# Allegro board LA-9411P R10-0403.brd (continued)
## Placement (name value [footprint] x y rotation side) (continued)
PR620  -  [R_0402]  313.93 168.74 270 bottom
PR621  -  [R0402_0OHM]  309.35 168.74 270 bottom
PR622  -  [R_1206]  294.81 171.64 0 bottom
PR623  -  [R_0402]  307.2 151.83 90 bottom
PR624  -  [R_0402]  308.21 151.83 90 bottom
PR625  -  [R0402_0OHM]  308.85 171.03 270 top
PR626  -  [R_0402]  307.2 155.03 270 bottom
PR627  -  [R_0402]  316.29 165.75 180 top
PR628  -  [R0402_0OHM]  307.58 168.74 270 bottom
PR629  -  [R0402_0OHM]  316.29 165.75 180 bottom
PR631  -  [R_0402]  316.29 164.73 180 bottom
PR632  -  [R_0402]  313.29 164.22 180 top
PR633  -  [R_0402]  315.37 163.72 0 bottom
PR634  -  [R_0402]  294.42 144.69 0 top
PR635  -  [R0402_0OHM]  305.11 162.45 180 top
PR636  -  [R0402_0OHM]  304.2 162.45 0 bottom
PR637  -  [R_0402]  313.29 163.08 180 top
PR638  -  [R_0402]  315.37 162.7 0 bottom
PR639  -  [R_0402]  315.37 160.67 0 top
PR640  -  [R_0402]  315.37 159.65 0 bottom
PR641  -  [R0402_0OHM]  307.2 157.82 270 bottom
PR642  -  [R_0402]  316.29 160.67 180 bottom
PR643  -  [R0402_0OHM]  308.21 157.82 270 bottom
PR644  -  [R_0402]  313.29 162.19 180 top
PR645  -  [R_0402]  309.23 157.82 270 bottom
PR646  -  [R_0402]  314.31 161 270 top
PR647  -  [R_0402]  311.7 154.52 270 bottom
PR648  -  [R_0402]  310.62 154.52 270 top
PR649  -  [R_0603]  303.7 158.38 0 bottom
PR650  -  [R0402_0OHM]  313 157.02 90 top
PR651  -  [R_0402]  303.13 151.83 90 bottom
PR652  -  [R_0402]  304.15 151.83 90 bottom
PR653  -  [R_1206]  290.34 147.38 0 bottom
PR654  -  [R_0402]  305.16 151.83 90 bottom
PR655  -  [R_0402]  310.62 154.52 270 bottom
PR656  -  [R_0402]  304.15 154.11 90 bottom
PR657  -  [R0402_0OHM]  311.51 156.91 90 bottom
PR658  -  [R_0402]  312.4 156.91 90 bottom
PR659  -  [R_0402]  310.62 157.82 270 bottom
PR679  -  [R_0402]  198.48 89.6 90 top
PR680  -  [R_1206]  193.59 90.06 0 top
PR681  -  [R0402_0OHM]  202.19 92.8 270 top
PR682  -  [R_0402]  200.16 91.88 90 top
PR683  -  [R_0402]  200.77 97.88 270 top
PR684  -  [R_0402]  198.74 96.96 90 top
PR685  -  [R_0402]  280.53 136.99 270 top
PR686  -  [R_0805]  280.69 141.36 0 top
PR687  -  [R_0402]  281.8 129.48 90 top
PR688  -  [R0402_0OHM]  279.51 136.99 270 top
PR689  -  [R_0402]  280.53 132.02 90 top
PR690  -  [R_0402]  279.51 134.96 270 top
PR691  -  [R_0402]  315.37 164.73 0 top
PR692  -  [R_0402]  315.12 158.47 0 bottom
PR693  -  [R_0402]  315.96 157.44 270 bottom
PR696  -  [R0402_0OHM]  315.07 157.44 270 bottom
PR697  -  [R_0402]  317.44 157.44 270 bottom
PR700  -  [R0402_0OHM]  154.21 161.23 90 top
PR701  -  [R_1206_4P-D]  129.87 173.75 180 top
PR702  -  [R0402_0OHM]  111.62 164.53 90 top
PR703  -  [R_0402]  113.14 165.44 270 top
PR704  -  [R0402_0OHM]  80.21 190.39 0 top
PR705  -  [R0402_0OHM]  80.21 189.37 0 top
PR706  -  [R_0402]  109.33 165.44 270 top
PR707  -  [R_0402]  114.16 165.44 270 top
PR708  -  [R_0805]  84.02 187.59 180 top
PR709  -  [R0402_0OHM]  108.31 164.53 90 top
PR710  -  [R0402_0OHM]  104.81 160.67 0 top
PR713  -  [R_0402]  73.1 186.84 180 top
PR714  -  [R_0402]  75.32 185.34 0 bottom
PR715  -  [R_0603]  82.71 182.77 0 top
PR716  -  [R_1206_4P-D]  115.13 176.03 180 top
PR717  -  [R0402_0OHM]  75.22 188.48 0 top
PR718  -  [R0402_0OHM]  77.33 180.43 270 top
PR719  -  [R0402_0OHM]  76.31 180.43 270 top
PR720  -  [R_0402]  72.2 185.47 0 top
PR721  -  [R_1206]  93.75 172.12 0 bottom
PR722  -  [R_0402]  75.29 180.43 270 top
PR723  -  [R_0402]  91.25 168.03 180 top
PR724  -  [R0402_0OHM]  96.96 159.22 180 top
PR725  -  [R_0402]  93.2 166.43 90 bottom
PR726  -  [R_0402]  90.33 167.14 0 top
PR727  -  [R_0402]  105.82 162.19 0 top
PR728  -  [R_0402]  90.33 163.59 0 top
PR729  -  [R_0402]  106.74 163.21 180 top
PR730  -  [R_0402]  91.25 166.26 180 top
PR731  -  [R_0402]  93.2 165.44 270 bottom
PR732  -  [R_0402]  102.42 163.21 180 top
PR733  -  [R_0402]  102.42 165.24 180 top
PR734  -  [R_0402]  102.42 166.26 180 top
PR735  -  [R_0402]  102.42 167.27 180 top
PR736  -  [R_0402]  104.81 158.64 0 top
PR737  -  [R0402_0OHM]  101.51 166.26 0 bottom
PR738  -  [R_0402]  101.51 162.19 0 top
PR739  -  [R_0402]  101.51 165.24 0 bottom
PR740  -  [R_0402]  101.51 167.27 0 bottom
PR741  -  [R_0402]  80.88 182.23 270 top
PR742  -  [R_1206]  82.66 187.65 270 bottom
PR743  -  [R_0402]  75.32 187.12 0 bottom
PR744  -  [R_0402]  105.72 159.65 180 top
PR745  -  [R0402_0OHM]  72.2 182.82 0 top
PR746  -  [R_0402]  72.2 183.71 0 top
PR747  -  [R_0402]  72.2 184.59 0 top
PR748  -  [R_0402]  87.28 164.67 180 top
PR749  -  [R_0402]  92.74 170.07 0 top
PR800  -  [R_0402]  239.17 84.98 0 top
PR801  -  [R_0402]  54.42 190.77 180 top
PR802  -  [R_0402]  241.61 89.93 180 top
PR803  -  [R_0402]  241.92 84.01 90 top
PR804  -  [R_0402]  239.33 89.93 180 top
PR805  -  [R_0402]  241.92 81.98 90 top
PR806  -  [R_0402]  241.36 85.86 180 top
PR807  -  [R_0402]  56.24 187.79 270 top
PR808  -  [R_0402]  239.33 85.86 180 top
PR809  -  [R_0603]  242.93 73.29 180 top
PR810  -  [R_0402]  45.83 188.4 90 top
PR811  -  [R0402_0OHM]  157.64 168.15 0 top
PR812  -  [R0402_0OHM]  51.62 185.94 180 top
PR813  -  [R_0402]  123.15 182.12 270 bottom
PR814  -  [R_0402]  119.87 172.4 90 top
PR815  -  [R_0402]  122.03 173.32 270 bottom
PR816  -  [R_0402]  118.09 167.45 90 bottom
PR817  -  [R_0402]  127.62 185.48 90 top
PR818  -  [R_0402]  122.08 172.86 180 top
PR819  -  [R_0402]  78.09 172.05 270 top
PR820  -  [R0402_0OHM]  70.9 170.32 0 top
PR821  -  [R_0603]  133.52 186.45 180 bottom
PR822  -  [R_0402]  122.08 171.84 180 top
PR823  -  [R_0402]  65.39 171.39 90 top
PR824  -  [R_0402]  62.9 173.88 0 top
PR825  -  [R0402_0OHM]  63.53 170.32 0 top
PR826  -  [R_0402]  53.07 171.89 90 top
PR827  -  [R_0402]  53.07 174.05 90 top
PR828  -  [R_0402]  146.19 178.38 180 top
PR829  -  [R_0402]  59.7 175.74 270 top
PR830  -  [R_0402]  152.33 179.73 270 top
PR831  -  [R0805_0OHM]  144.28 166.73 0 top
PR832  -  [R0402_0OHM]  145.19 168.03 0 top
PR833  -  [R0402_0OHM]  147.01 165.25 270 top
PR834  -  [R_0402]  160.64 168.34 90 top
PR835  -  [R_0805]  147.68 160.32 90 top
PR836  -  [R_0402]  161.1 177.69 180 top
PR837  -  [R_0402]  161.65 168.34 90 top
PR838  -  [R0402_0OHM]  145.19 169.81 0 top
PR839  -  [R_0402]  53.07 177.25 270 top
PR840  -  [R_0402]  53.07 178.5 90 top
PR841  -  [R_0402]  161.1 178.57 180 top
PR842  -  [R_0402]  162.67 168.34 90 top
PR843  -  [R0402_0OHM]  147.18 173.42 90 top
PR844  -  [R_0402]  152.29 176.06 90 top
PR845  -  [R_0402]  162.21 177.81 0 top
PR846  -  [R_0402]  156.24 160.22 270 top
PR847  -  [R0402_0OHM]  151.56 161.14 90 top
PR848  -  [R_0402]  163.69 168.34 90 top
PR849  -  [R_0402]  59.71 177.44 90 top
PR850  -  [R0402_0OHM]  148.19 173.42 90 top
PR851  -  [R_0402]  164.7 168.34 90 top
PR852  -  [R_0402]  163.99 177.81 0 top
PR853  -  [R_0402]  166.73 168.34 90 top
PR854  -  [R0805_0OHM]  152.87 160.79 90 top
PR855  -  [R0402_0OHM]  151.24 173.42 90 top
PR856  -  [R_0402]  167.75 168.34 90 top
PR857  -  [R0402_0OHM]  152.26 173.42 90 top
PR858  -  [R_0402]  153.2 176.07 90 top
PR859  -  [R0402_0OHM]  155.23 161.23 90 top
PR860  -  [R0402_0OHM]  153.27 173.42 90 top
PR861  -  [R_0402]  167.42 177.94 0 top
PR862  -  [R0402_0OHM]  156.24 161.23 90 top
PR863  -  [R_0402]  154.29 173.42 90 top
PR864  -  [R_0402]  168.33 171.84 180 top
PR865  -  [R_0402]  167.42 176.92 0 top
PR866  -  [R0402_0OHM]  158.56 169.16 180 top
PR867  -  [R_0402]  167.42 175.91 0 top
PR868  -  [R0402_0OHM]  157.64 170.18 0 top
PR869  -  [R_0402]  156.4 173.42 90 top
PR870  -  [R_0402]  155.3 174.33 270 top
PR871  -  [R_0402]  167.42 174.89 0 top
PR872  -  [R0402_0OHM]  172.07 170.01 270 top
PR873  -  [R_0402]  167.42 173.88 0 top
PR874  -  [R_0402]  157.64 171.2 0 top
PR875  -  [R_0402]  157.46 173.42 90 top
PR876  -  [R_0402]  167.42 172.86 0 top
PR877  -  [R0805_0OHM]  157.49 166.83 0 top
PR878  -  [R_0402]  156.24 170.83 0 bottom
PR879  -  [R_0402]  157.16 172.81 180 bottom
PR880  -  [R_0402]  156.24 171.84 0 bottom
PR881  -  [R_0402]  65.85 175.67 90 top
PR882  -  [R0402_0OHM]  58.66 172.47 90 top
PR883  -  [R_0402]  155.86 177.7 0 bottom
PR884  -  [R_0402]  57.91 174.83 90 top
PR885  -  [R_0402]  57.91 178.36 270 top
PR886  -  [R0402_0OHM]  58.8 174.83 90 top
PR887  -  [R0402_0OHM]  58.82 178.36 270 top
PR888  -  [R0402_0OHM]  48.36 190.49 0 top
PR889  -  [R_0402]  116.11 172.94 90 bottom
PR890  -  [R0402_0OHM]  116.11 172.1 270 bottom
PR891  -  [R_0402]  132.88 187.27 0 top
PR892  -  [R0402_0OHM]  132.88 188.18 0 top
PR893  -  [R0402_0OHM]  145.19 168.92 0 top
PR894  -  [R_0402]  153.22 178.82 90 top
PR895  -  [R0402_0OHM]  148.22 181.84 0 top
PR896  -  [R_0402]  40.11 176.06 0 top
PR897  -  [R_0402]  41.03 177.06 180 top
PU1  -  [74LVC1G3157GW_SC-88-6]  154.4 176.3 270 bottom
PU100  -  [TPS51225CRUKR_QFN20_3X3]  151.53 4.81 180 bottom
PU200  -  [RT8207MZQW_WQFN20_3X3]  209.62 12.31 0 top
PU300  -  [TPS51212DSCR_SON10_3X3]  238.11 7.12 0 top
PU400  -  [SY8033BDBC_DFN10_3X3]  235.65 103.79 90 top
PU500  -  [ISL95812HRZ-T_QFN32_4X4]  118.21 153.43 90 bottom
PU501  -  [ISL6208BCRZ-T_QFN8_2X2]  160.91 153.69 90 top
PU600  -  [ISL62883CHRTZ-T_TQFN40_5X5]  312.72 164.75 270 bottom
PU602  -  [SY8036DBC_DFN10_3X3]  196.87 92.32 0 top
PU603  -  [SY8033BDBC_DFN10_3X3]  283.68 134.71 180 top
PU700  -  [BQ24738RGRR_QFN20_3P5X3P5]  78.58 186.4 180 top
PU701  -  [AS393MTR-G1_SO8]  93.67 167.78 270 top
PU702  -  [LM358DR2G_SOIC8]  103.19 157.24 270 top
PU703  -  [INA199A2DCKR_SC70-6]  108.43 160.58 0 top
PU704  -  [TC7SH08FU_SSOP5]  91.01 158.64 0 top
PU800  -  [CD3301RHHR_QFN36_6X6]  149.75 164.63 0 top
PU801  -  [TC7SH08FU_SSOP5]  47.72 182.83 0 top
PU802  -  [TC7SH08FU_SSOP5]  50.51 182.83 0 top
PU803  -  [74AHC1G32GW_SOT353-5]  47.97 187.4 0 top
PU804  -  [TC7SH08FU_SSOP5]  50.77 187.4 0 top
PU805  -  [TC7SH08FU_SSOP5]  76.96 173.17 180 top
PU806  -  [TC7SH08FU_SSOP5]  72.39 173.3 180 top
PU807  -  [TC7SH08FU_SSOP5]  62.41 172.75 270 top
PU808  -  [CD3302RUYR_QFN28_4X4]  161.6 171.65 0 top
PU809  -  [TC7SH08FU_SSOP5]  37.2 174.9 180 top
Q1  -  [MMBT3904WT1G_SC70-3]  145.97 96.15 90 bottom
Q2  -  [MMBT3904WT1G_SC70-3]  310.6 151.84 180 top
Q3  -  [MMBT3904WT1G_SC70-3]  161.15 132.03 0 top
Q4  -  [PMST3904_SOT323-3]  279.76 122.91 180 top
Q5  -  [L2N7002WT1G_SC-70-3]  200.94 172.73 270 bottom
Q6  -  [L2N7002WT1G_SC-70-3]  179.32 175.15 90 bottom
Q21  -  [FDC654P-G_SSOT-6]  180.73 148.41 270 bottom
Q22  -  [L2N7002WT1G_SC-70-3]  180.45 143.84 180 bottom
Q23  -  [DMG2301U-7_SOT23-3]  192.78 165.99 90 top
Q29  -  [DMN66D0LDW-7_SOT363-6]  123.35 7.46 270 bottom
Q44  -  [L2N7002WT1G_SC-70-3]  263.7 135.52 90 bottom
Q45  -  [L2N7002WT1G_SC-70-3]  287.2 126.63 90 top
Q47  -  [L2N7002WT1G_SC-70-3]  112.82 154.57 270 top
Q48  -  [L2N7002WT1G_SC-70-3]  316.78 214.77 90 bottom
Q52  -  [DMN66D0LDW-7_SOT363-6]  231.89 21.15 180 bottom
Q59  -  [L2N7002WT1G_SC-70-3]  316.78 212.23 90 bottom
Q63  -  [SI4164DY-T1-GE3_SO8]  222.74 22.59 0 bottom
Q70  -  [L2N7002WT1G_SC-70-3]  217.47 21.98 90 bottom
Q71  -  [L2N7002WT1G_SC-70-3]  137.52 69.55 180 top
Q72  -  [L2N7002WT1G_SC-70-3]  189.55 19.48 90 top
Q74  -  [DMN66D0LDW-7_SOT363-6]  330.63 160.05 270 top
Q75  -  [PDTA114EU_SC70-3]  329.08 157.11 270 top
Q76  -  [L2N7002WT1G_SC-70-3]  231.22 43.99 90 bottom
Q77  -  [L2N7002WT1G_SC-70-3]  347.96 199.29 90 bottom
Q78  -  [L2N7002WT1G_SC-70-3]  278.05 176.92 270 bottom
Q79  -  [PDTA114EU_SC70-3]  324.21 165.53 0 top
Q80  -  [PDTA114EU_SC70-3]  52.94 194.74 0 top
Q81  -  [PDTA114EU_SC70-3]  321.89 215.02 270 bottom
Q82  -  [PDTA114EU_SC70-3]  55.48 194.74 0 top
Q83  -  [DMN66D0LDW-7_SOT363-6]  328.42 165.17 180 top
Q84  -  [DMN66D0LDW-7_SOT363-6]  326.82 214.25 90 bottom
Q85  -  [L2N7002WT1G_SC-70-3]  319.9 124.66 0 top
Q86  -  [PDTA114EU_SC70-3]  58.02 194.74 0 top
Q88  -  [L2N7002WT1G_SC-70-3]  317.28 124.66 0 top
Q89  -  [L2N7002WT1G_SC-70-3]  276.65 172.86 90 bottom
Q100  -  [L2N7002WT1G_SC-70-3]  321.67 165.94 180 top
Q106  -  [DMN66D0LDW-7_SOT363-6]  340.91 162.46 270 bottom
Q123  -  [DMN66D0LDW-7_SOT363-6]  229.33 47.64 0 bottom
Q124  -  [DMN66D0LDW-7_SOT363-6]  271.52 171.91 180 bottom
Q324  -  [L2N7002WT1G_SC-70-3]  347.58 162 180 top
Q325  -  [DMN66D0LDW-7_SOT363-6]  311.14 204.37 0 top
Q326  -  [L2N7002WT1G_SC-70-3]  309.7 205.98 90 bottom
Q327  -  [DMN66D0LDW-7_SOT363-6]  350.02 170.73 0 top
QC1  -  [L2N7002WT1G_SC-70-3]  142.28 68.21 270 top
QC3  -  [L2N7002WT1G_SC-70-3]  163.69 128.18 0 top
QC4  -  [DMN66D0LDW-7_SOT363-6]  142.28 70.36 90 top
QC5  -  [L2N7002WT1G_SC-70-3]  141.33 61.29 0 top
QC6  -  [AO4304L_SO8]  150.6 72.57 180 top
QD6  -  [DMN66D0LDW-7_SOT363-6]  122.6 29.28 270 top
QD7  -  [L2N7002WT1G_SC-70-3]  167.02 17.63 270 top
QD9  -  [L2N7002WT1G_SC-70-3]  129.55 17.94 90 top
QH2  -  [BSS138W-7-F_SOT323-3]  186.74 68.54 135 bottom
QH3  -  [L2N7002WT1G_SC-70-3]  194.08 59.41 225 top
QH4  -  [DMN66D0LDW-7_SOT363-6]  187.4 62.92 45 bottom
QV1  -  [SI4164DY-T1-GE3_SO8]  192.77 106.67 180 top
QV2  -  [L2N7002WT1G_SC-70-3]  184.19 104.28 270 top
QV3  -  [MMBT3904WT1G_SC70-3]  247.83 114.95 270 top
QV4  -  [MMBT3906WT1G_SC70-3]  244.52 114.3 90 top
QV5  -  [L2N7002WT1G_SC-70-3]  179.08 108.04 90 top
QV6  -  [L2N7002WT1G_SC-70-3]  179.08 110.6 90 top
QV7  -  [PMST3904_SOT323-3]  249.96 112.15 270 top
QV8  -  [PMST3904_SOT323-3]  243.29 135.2 0 top
QV11  -  [L2N7002WT1G_SC-70-3]  184.19 106.77 270 top
R2  -  [R0402_0OHM]  328.02 193.99 90 top
R3  -  [R_0402]  259.35 49.86 0 top
R4  -  [R0402_0OHM]  329.04 193.99 90 top
R5  -  [R0402_0OHM]  354.69 156.32 270 top
R6  -  [R0402_0OHM]  336.41 157.82 270 top
R7  -  [R_0402]  190.86 26.23 90 top
R8  -  [R_0402]  192.13 26.23 90 top
R9  -  [R_0402]  193.4 26.23 90 top
R10  -  [R0402_0OHM]  328.02 184.85 90 top
R11  -  [R0402_0OHM]  329.04 184.85 90 top
R12  -  [R0402_0OHM]  330.06 184.85 90 top
R13  -  [R0402_0OHM]  331.07 184.85 90 top
R14  -  [R_0402]  31.05 183.02 180 top
R15  -  [R0402_0OHM]  352.38 184.82 90 bottom
R16  -  [R_0402]  31.05 184.04 180 top
R17  -  [R_0402]  301.09 111.77 90 top
R18  -  [R_0402]  40.95 183.02 180 top
R19  -  [R_0402]  40.95 184.04 180 top
R20  -  [R_0402]  40.95 186.32 180 top
R21  -  [R_0402]  40.95 185.31 180 top
R22  -  [R0402_0OHM]  334.2 218.07 180 top
R23  -  [R0402_0OHM]  300.87 113.58 0 top
R24  -  [R0402_0OHM]  300.87 114.44 0 top
R25  -  [R0402_0OHM]  296.99 195.26 90 top
R26  -  [R0402_0OHM]  334.2 219.09 180 top
R27  -  [R0402_0OHM]  343.72 219.09 180 top
R28  -  [R0402_0OHM]  343.72 220.1 180 top
R29  -  [R0402_0OHM]  343.72 222.14 180 top
R30  -  [R_0402]  117.66 89.8 180 bottom
R31  -  [R0402_0OHM]  343.72 221.12 180 top
R32  -  [R0402_0OHM]  340.36 194.96 90 top
R33  -  [R0402_0OHM]  341.37 194.96 90 top
R34  -  [R0402_0OHM]  340.36 186.19 90 top
R35  -  [R0402_0OHM]  341.37 186.19 90 top
R36  -  [R0402_0OHM]  343.4 186.19 90 top
R37  -  [R0402_0OHM]  342.39 186.19 90 top
R38  -  [R_0402]  117.66 88.79 180 bottom
R39  -  [R_0402]  352.05 166.69 90 top
R40  -  [R0402_0OHM]  352.97 166.69 90 top
R45  -  [R0402_0OHM]  297.86 195.26 90 top
R46  -  [R0402_0OHM]  300.19 195.26 90 top
R47  -  [R0402_0OHM]  301.1 195.26 90 top
R48  -  [R0402_0OHM]  303.13 195.26 90 top
R49  -  [R0402_0OHM]  304.02 195.26 90 top
R50  -  [R0402_0OHM]  306.43 195.26 90 top
R51  -  [R_0402]  283.07 122.59 270 top
R52  -  [R_0402]  294.92 109.87 0 top
R53  -  [R0402_0OHM]  307.32 195.26 90 top
R54  -  [R0603_0OHM]  350.76 183.21 270 bottom
R55  -  [R_0402]  280.5 125.79 180 top
R56  -  [R0603_0OHM]  349.86 179.01 90 bottom
R57  -  [R0603_0OHM]  353.77 174.33 270 top
R58  -  [R0603_0OHM]  354.25 168 90 bottom
R61  -  [R_0402]  185.02 168.59 90 top
R62  -  [R_0402]  18.6 205.37 180 bottom
R63  -  [R_0402]  18.6 204.36 180 bottom
R64  -  [R_0402]  18.6 206.64 180 bottom
R65  -  [R_0402]  27.8 207.61 270 top
R67  -  [R0402_0OHM]  22.72 192.72 90 top
R68  -  [R_0402]  18.6 207.66 180 bottom
R69  -  [R_0402]  23.48 195.52 90 top
R70  -  [R_0402]  24.49 195.52 90 top
R71  -  [R_0402]  18.6 201.56 180 bottom
R72  -  [R_0402]  21.32 203.42 270 top
R73  -  [R_0402]  16.82 206.39 180 top
R74  -  [R_0402]  18.6 202.58 180 bottom
R75  -  [R_0402]  32.16 199.28 0 top
R76  -  [R_0402]  23.73 206.69 90 top
R77  -  [R_0402]  18.6 199.02 180 bottom
R78  -  [R_0402]  18.6 200.04 180 bottom
R79  -  [R_0402]  26.78 207.61 270 top
R80  -  [R_0402]  24.75 207.61 270 top
R81  -  [R_0402]  26.78 209.49 90 top
R82  -  [R_0402]  24.75 209.49 90 top
R84  -  [R_0402]  16.82 207.4 180 top
R85  -  [R_0402]  25.51 195.52 90 top
R86  -  [R_0402]  25.76 207.61 270 top
R87  -  [R_0402]  25.51 193.64 270 top
R88  -  [R_0402]  25.76 209.49 90 top
R100  -  [R_0402]  169.07 141.62 0 top
R101  -  [R_0402]  169.07 134.51 0 top
R102  -  [R_0402]  173.59 145.16 90 top
R103  -  [R_0402]  174.93 145.16 90 top
R104  -  [R0402_0OHM]  172.32 132.42 270 top
R105  -  [R_0402]  172.58 146.08 270 top
R106  -  [R_0402]  172.58 148.68 270 top
R107  -  [R_0402]  176.89 146.65 270 top
R108  -  [R_0402]  175.88 145.73 90 top
R109  -  [R0402_0OHM]  175.62 126.68 90 top
R110  -  [R_0402]  169.99 139.59 180 bottom
R111  -  [R_0402]  169.07 140.6 0 bottom
R112  -  [R_0402]  174.61 143.26 90 top
R113  -  [R_0402]  173.59 143.26 90 top
R114  -  [R_0402]  176.64 126.68 90 top
R115  -  [R0402_0OHM]  174.94 158.86 270 top
R152  -  [R0402_0OHM]  315.58 192.72 90 bottom
R153  -  [R_0402]  318.17 217.06 0 bottom
R154  -  [R0603_0OHM]  317.1 194.39 90 top
R159  -  [R_0402]  179.15 164.35 180 bottom
R160  -  [R_0402]  179.15 165.37 180 bottom
R169  -  [R_0402]  337.68 177.48 90 top
R198  -  [R_0402]  348.26 165.35 90 bottom
R199  -  [R_0402]  347.35 165.35 90 bottom
R209  -  [R_0402]  348.26 167.13 90 bottom
R210  -  [R_0402]  347.35 167.13 90 bottom
R392  -  [R_0402]  282.42 101.73 270 top
R407  -  [R_0402]  291.19 125.54 90 top
R415  -  [R_0402]  199.83 171.21 90 bottom
R416  -  [R_0402]  180.6 176.9 180 bottom
R418  -  [R_0402]  297.12 112.66 0 top
R420  -  [R_0402]  295.83 112.66 180 top
R422  -  [R_0402]  177.71 144.16 0 bottom
R423  -  [R_0402]  179.99 145.17 0 bottom
R424  -  [R_0402]  290.3 126.45 270 top
R427  -  [R_0402]  190.52 167.5 270 bottom
R428  -  [R_0402]  189.5 167.5 270 bottom
R491  -  [R_0402]  178.8 177.89 270 bottom
R492  -  [R_0402]  194.17 177.63 270 bottom
R493  -  [R_0402]  254.94 31.81 90 top
R501  -  [R_0402]  121.78 10.1 90 bottom
R502  -  [R_0402]  119.49 14.82 270 bottom
R503  -  [R_0402]  118.98 6.54 90 bottom
R506  -  [R_0402]  112.84 36.46 180 top
R508  -  [R_0402]  120 6.54 90 bottom
R509  -  [R_0402]  218.55 41.24 270 bottom
R510  -  [R_0402]  226.73 44.15 0 bottom
R512  -  [R_0402]  220.96 37.99 90 bottom
R513  -  [R_0402]  226.73 45.17 0 bottom
R514  -  [R_0402]  231 49.94 270 bottom
R515  -  [R_0402]  226.73 46.18 0 bottom
R516  -  [R_0402]  112.84 45.61 180 top
R517  -  [R_0402]  170.52 157.91 90 top
R518  -  [R_0402]  272.97 63.06 90 top
R545  -  [R_0402]  316.59 205.32 270 bottom
R546  -  [R_0402]  317.61 205.32 270 bottom
R548  -  [R_0805]  316.85 189.97 270 bottom
R549  -  [R_0402]  319.64 192.72 90 bottom
R550  -  [R_0402]  327.31 129.92 180 top
R551  -  [R0402_0OHM]  313.55 205.32 270 bottom
R552  -  [R0402_0OHM]  315.58 205.32 270 bottom
R553  -  [R_0402]  321.67 192.72 90 bottom
R554  -  [R_0402]  327.31 128.05 180 top
R555  -  [R0402_0OHM]  318.63 192.72 90 bottom
R556  -  [R_0402]  316.59 192.72 90 bottom
R557  -  [R_0402]  317.61 193.64 270 bottom
R558  -  [R_0402]  321.62 191.38 180 bottom
R559  -  [R0402_0OHM]  321.62 190.46 180 bottom
R560  -  [R_0402]  322.66 135.65 270 top
R561  -  [R_0402]  314.56 204.41 90 bottom
R562  -  [R_0402]  309.74 193.64 270 bottom
R563  -  [R_0402]  326.4 131.91 0 top
R564  -  [R_0402]  319.16 132.92 180 top
R565  -  [R_0402]  318.24 130.9 0 top
R566  -  [R_0402]  319.32 189.7 270 bottom
R567  -  [R_0402]  318.24 130.02 0 top
R571  -  [R_0402]  308.72 219.29 270 bottom
R572  -  [R_0402]  301.35 219.29 270 bottom
R573  -  [R_0402]  307.7 219.29 270 bottom
R574  -  [R_0402]  300.08 219.29 270 bottom
R585  -  [R_0402]  267.27 82.09 180 top
R589  -  [R_0402]  267.27 81.17 180 top
R657  -  [R_0402]  296.45 139.59 0 top
R676  -  [R_0402]  256.19 44.59 0 top
R677  -  [R_0402]  253.04 50.5 225 top
R693  -  [R_0402]  261.48 175.7 90 bottom
R694  -  [R_0402]  266.56 173.8 90 bottom
R695  -  [R_0402]  273.16 188.4 90 top
R703  -  [R0402_0OHM]  262.49 175.7 90 bottom
R704  -  [R0402_0OHM]  337.93 203.03 270 top
R705  -  [R_0402]  270.87 176.62 270 bottom
R706  -  [R_0402]  269.86 176.62 270 bottom
R707  -  [R0402_0OHM]  272.14 188.4 90 top
R716  -  [R_0402]  284.34 182.82 90 bottom
R717  -  [R0402_0OHM]  268.28 38.75 180 top
R718  -  [R_0402]  271.89 176.62 270 bottom
R719  -  [R_0402]  344.79 199.48 270 bottom
R720  -  [R_0402]  272.91 176.62 270 bottom
R724  -  [R_0402]  319.39 126.23 90 top
R725  -  [R_0402]  266.04 172.63 180 bottom
R726  -  [R_0402]  325.15 198.55 270 top
R727  -  [R_0402]  318.42 126.23 90 top
R728  -  [R_0402]  264.22 173.55 270 bottom
R729  -  [R_0402]  263.32 173.55 270 bottom
R731  -  [R_0402]  279.81 30.37 0 top
R732  -  [R_0402]  279.81 29.35 0 top
R733  -  [R_0402]  287.38 182.82 90 bottom
R734  -  [R_0402]  267.37 37.78 0 top
R735  -  [R_0402]  230.84 19.2 90 bottom
R736  -  [R_0402]  325.48 218.12 90 bottom
R737  -  [R_0402]  268.59 188.4 90 top
R738  -  [R0402_0OHM]  275.45 60.13 90 top
R739  -  [R_0402]  268.84 176.62 270 bottom
R740  -  [R_0402]  326.5 218.12 90 bottom
R744  -  [R0402_0OHM]  231.86 19.2 90 bottom
R747  -  [R0402_0OHM]  317.46 127.14 270 top
R748  -  [R_0402]  326.4 130.9 0 top
R749  -  [R_0402]  317.36 128.19 90 top
R751  -  [R_0402]  262.03 137.3 0 bottom
R752  -  [R_0402]  262.95 133.74 180 bottom
R753  -  [R_0402]  249.84 135.52 0 bottom
R754  -  [R_0402]  262.95 139.59 180 bottom
R755  -  [R_0402]  200.77 189.32 270 top
R756  -  [R_0402]  199.5 177.96 270 bottom
R757  -  [R_0402]  176.89 177.91 270 bottom
R758  -  [R_0402]  177.4 190.59 270 top
R759  -  [R_0402]  280.03 119.52 270 top
R760  -  [R_0402]  259.35 58.62 0 top
R761  -  [R_0402]  263.63 43.67 90 top
R762  -  [R_0402]  264.65 43.67 90 top
R763  -  [R_0402]  277.32 49.76 180 top
R767  -  [R_0402]  259.35 55.57 0 top
R768  -  [R_0402]  259.35 57.6 0 top
R769  -  [R_0402]  259.35 54.56 0 top
R771  -  [R_0402]  277.45 53.94 180 top
R772  -  [R_0402]  267.68 40.67 90 top
R774  -  [R_0402]  266.68 41.57 270 top
R775  -  [R_0402]  265.67 43.66 90 top
R776  -  [R_0402]  277.32 47.83 180 top
R777  -  [R_0402]  268.57 61.75 270 top
R778  -  [R_0402]  259.35 53.54 0 top
R780  -  [R_0402]  267.57 61.81 270 top
R782  -  [R_0402]  277.45 56.02 180 top
R786  -  [R_0402]  277.45 52.95 180 top
R789  -  [R_0402]  274.43 61.05 270 top
R790  -  [R_0402]  270.73 43.65 90 top
R791  -  [R_0402]  263.13 61.76 270 top
R793  -  [R_0402]  276.53 52.01 0 top
R794  -  [R_0402]  262.11 60.81 90 top
R795  -  [R_0402]  265.52 60.8 90 top
R796  -  [R_0402]  259.35 48.91 0 top
R798  -  [R_0402]  259.35 59.64 0 top
R799  -  [R_0402]  285.21 125.74 0 top
R800  -  [R_0402]  268.69 43.65 90 top
R802  -  [R0402_0OHM]  273.41 61.56 270 top
R803  -  [R_0402]  269.71 44.6 270 top
R804  -  [R_0402]  276.67 57.54 0 top
R805  -  [R_0402]  263.63 40.62 90 top
R806  -  [R_0402]  277.32 46.81 180 top
R807  -  [R_0402]  264.65 40.62 90 top
R810  -  [R_0402]  294.42 106.18 0 top
R811  -  [R_0402]  296.21 106.2 270 top
R812  -  [R_0402]  279.89 110.24 90 top
R814  -  [R_0402]  277.81 113.3 180 top
R816  -  [R_0402]  318.17 215.02 0 bottom
R817  -  [R_0402]  286.94 124.8 270 top
R818  -  [R_0402]  285.35 100.52 90 top
R819  -  [R_0402]  294.43 108.01 90 top
R820  -  [R_0402]  285.8 105.35 90 top
R822  -  [R_0402]  284.46 98.74 90 top
R825  -  [R_0402]  296.2 108.85 0 top
R826  -  [R_0402]  261.22 31.94 90 top
R827  -  [R_0402]  279.05 108.88 0 top
R828  -  [R_0402]  278.11 108.36 270 top
R829  -  [R_0402]  285.35 98.74 90 top
R830  -  [R0402_0OHM]  285.78 102.87 90 top
R831  -  [R_0402]  245.93 35.95 180 top
R834  -  [R0402_0OHM]  282.35 124.54 0 top
R835  -  [R_0402]  284.91 105.35 90 top
R836  -  [R_0402]  289.34 100.47 0 top
R837  -  [R_0402]  282.35 125.42 0 top
R838  -  [R_0402]  295.83 111.77 180 top
R839  -  [R0402_0OHM]  289.45 106.26 270 top
R840  -  [R0402_0OHM]  275.2 122.19 270 top
R841  -  [R_0402]  297.12 111.77 0 top
R843  -  [R_0402]  281.03 122.59 270 top
R845  -  [R_0402]  279.14 115.96 0 top
R846  -  [R_0402]  277.81 114.19 180 top
R847  -  [R_0402]  324.34 162.7 0 bottom
R848  -  [R_0402]  324.34 160.67 0 bottom
R849  -  [R_0402]  325.26 158.64 180 bottom
R850  -  [R_0402]  324.34 161.68 0 bottom
R851  -  [R_0402]  279.14 115.07 0 top
R852  -  [R_0402]  277.81 115.07 180 top
R853  -  [R0402_0OHM]  325.26 159.65 180 bottom
R854  -  [R_0402]  297.12 113.55 0 top
R855  -  [R_0402]  325.26 157.62 180 bottom
R856  -  [R_0402]  295.83 113.55 180 top
R864  -  [R_0402]  324.34 167.78 0 bottom
R866  -  [R0402_0OHM]  281.24 105.3 180 top
R869  -  [R_0402]  279.14 114.19 0 top
R870  -  [R_0402]  284.91 102.87 90 top
R871  -  [R_0402]  295.83 114.44 180 top
R872  -  [R_0402]  291.64 100.01 90 top
R874  -  [R_0402]  290.29 103.78 270 top
R875  -  [R_0402]  299.37 116.22 0 top
R876  -  [R_0402]  289.4 103.78 270 top
R878  -  [R_0402]  268.71 40.69 90 top
R879  -  [R_0402]  289.34 101.36 0 top
R880  -  [R_0402]  284.27 124.8 270 top
R881  -  [R_0402]  288.7 123.9 0 top
R882  -  [R_0402]  286.94 122.45 270 top
R884  -  [R_0402]  298.5 108.93 270 top
R885  -  [R_0402]  285.16 121.54 90 top
R887  -  [R_0402]  286.69 101.37 270 top
R888  -  [R_0402]  299.33 112.66 0 top
R889  -  [R_0402]  279.14 116.85 0 top
R892  -  [R_0402]  276.89 112.03 0 top
R894  -  [R_0402]  244.76 47.13 0 top
R895  -  [R_0402]  198.74 26.23 90 top
R899  -  [R_0402]  193.4 40.07 90 top
R901  -  [R_0402]  195.69 40.07 90 top
R902  -  [R_0402]  269.1 99.66 270 top
R903  -  [R_0402]  269.1 96.46 90 top
R909  -  [R_0402]  232.05 24.96 270 bottom
R920  -  [R_0402]  287.56 101.36 0 top
R925  -  [R_0402]  218.8 22.95 270 bottom
R926  -  [R_0402]  135.75 70.45 270 top
R927  -  [R_0603]  187.63 17.53 0 top
R930  -  [R_0402]  228.88 21.68 270 bottom
R931  -  [R_0402]  219.82 22.95 270 bottom
R932  -  [R_0402]  329.55 164.17 270 top
R934  -  [R_0402]  325.23 166.81 90 top
R936  -  [R_0402]  197.47 26.23 90 top
R937  -  [R_0402]  319.9 165.67 90 top
R938  -  [R_0402]  320.66 214.82 90 bottom
R940  -  [R_0402]  51.16 193.23 90 top
R949  -  [R_0402]  326.25 166.81 90 top
R951  -  [R_0402]  327.26 166.81 90 top
R952  -  [R_0402]  280.09 107.81 180 top
R953  -  [R_0402]  330.56 164.17 270 top
R954  -  [R_0402]  53.96 196.28 90 top
R955  -  [R_0402]  324.72 214.31 90 bottom
R957  -  [R_0402]  331.4 214.64 180 bottom
R958  -  [R_0402]  327.26 162.14 270 top
R988  -  [R_0402]  57.51 196.28 90 top
R989  -  [R_0402]  55.99 196.28 90 top
R1062  -  [R_0402]  188.95 166.55 180 top
R1066  -  [R_0402]  188.95 167.44 180 top
R1068  -  [R0402_0OHM]  292.51 106.95 270 top
R1069  -  [R_0402]  286.05 123.89 90 top
R1070  -  [R0402_0OHM]  276.65 124.46 90 top
R1076  -  [R_0402]  332.55 171.59 180 top
R1077  -  [R_0402]  335.09 172.61 180 top
R1079  -  [R_0402]  338.95 165.44 270 bottom
R1080  -  [R_0402]  337.93 165.44 270 bottom
R1081  -  [R_0402]  343.26 165.44 270 bottom
R1082  -  [R_0402]  344.28 165.44 270 bottom
R1084  -  [R_0402]  349.89 174.61 270 top
R1086  -  [R_0402]  336.91 162.65 270 top
R1088  -  [R_0402]  350.85 175.18 90 bottom
R1096  -  [R_0402]  334.17 170.57 0 top
R1097  -  [R_0402]  340.98 164.53 90 top
R1099  -  [R_0402]  336.66 178.4 270 top
R1100  -  [R_0402]  349.83 178 270 bottom
R1118  -  [R_0402]  299.33 111.77 0 top
R1119  -  [R_0402]  332.34 169.56 180 top
R1120  -  [R_0402]  334.17 167.53 0 top
R1125  -  [R_0402]  283.31 100.81 90 top
R1137  -  [R_0402]  179.89 155.08 180 top
R1138  -  [R_0402]  178.72 153.68 0 bottom
R1139  -  [R_0402]  180.91 148.93 270 top
R1141  -  [R_0402]  334.17 166.51 0 top
R1142  -  [R_0402]  332.55 170.57 180 top
R1144  -  [R0402_0OHM]  312.28 192.72 90 bottom
R1145  -  [R_0402]  352.67 168.48 90 bottom
R1146  -  [R_0402]  349.54 182.74 270 bottom
R1150  -  [R_0402]  25.71 181.5 180 bottom
R1151  -  [R_0402]  25.71 180.48 180 bottom
R1154  -  [R_0402]  280.35 49.92 180 top
R1156  -  [R_0402]  293.43 106.03 90 top
R1161  -  [R0603_0OHM]  261.73 94.18 90 top
R1162  -  [R_0603]  260.46 94.18 90 top
R1163  -  [R0603_0OHM]  267.1 97.17 180 top
R1164  -  [R0603_0OHM]  267.1 98.95 180 top
R1166  -  [R_0402]  296.53 211.14 90 bottom
R1167  -  [R_0402]  313.42 210.63 90 bottom
R1169  -  [R_0402]  299.39 108.93 270 top
R1171  -  [R_0402]  279.14 117.72 0 top
R1179  -  [R_0402]  279 110.24 90 top
R1180  -  [R0402_0OHM]  112.3 156.73 0 top
R1183  -  [R_0402]  229.98 49.94 270 bottom
R1187  -  [R0402_0OHM]  321.62 195.21 180 bottom
R1197  -  [R_0402]  286.69 98.68 90 top
R1530  -  [R_0402]  196.71 177.63 270 bottom
R1539  -  [R_0402]  195.69 177.63 270 bottom
R1583  -  [R_0402]  277.32 48.84 180 top
R1603  -  [R_0402]  330.82 219.14 90 bottom
R1604  -  [R_0402]  328.79 218.12 90 bottom
R1605  -  [R_0402]  327.77 218.12 90 bottom
R1606  -  [R_0402]  329.8 219.14 90 bottom
R1607  -  [R0402_0OHM]  170.7 161.26 180 top
R1608  -  [R_0402]  170.7 162.19 180 top
R1609  -  [R_0402]  25.71 183.27 180 bottom
R1610  -  [R_0402]  25.71 184.29 180 bottom
R1611  -  [R_0402]  227.95 21.68 270 bottom
R1612  -  [R_0402]  25.71 185.31 180 bottom
R1613  -  [R_0402]  25.71 186.32 180 bottom
R1614  -  [R_0402]  318.17 214.01 0 bottom
R1615  -  [R_0402]  302.05 188.37 90 bottom
R1616  -  [R0402_0OHM]  302.94 188.37 90 bottom
R1620  -  [R_0402]  170.7 160.35 180 top
R1622  -  [R_0402]  214.67 50.62 45 bottom
R1623  -  [R_0402]  212.52 47.57 135 bottom
R1624  -  [R_0402]  214.2 47.19 135 bottom
R1626  -  [R0402_0OHM]  318.17 218.07 0 bottom
R1629  -  [R_0402]  216.84 52.79 225 bottom
R1630  -  [R_0402]  214.16 48.47 315 bottom
R1631  -  [R0402_0OHM]  285.35 183.73 270 bottom
R1633  -  [R_0402]  286.37 183.73 270 bottom
R1635  -  [R_0402]  112.84 46.62 180 top
R1636  -  [R_0402]  211.9 46.93 135 bottom
R1640  -  [R_0402]  266.3 87.63 0 top
R1642  -  [R_0402]  343.9 165.32 270 top
R1653  -  [R_0402]  312.53 210.63 90 bottom
R1654  -  [R_0402]  338.95 164.53 90 top
R1655  -  [R0402_0OHM]  210.35 49.74 315 bottom
R1667  -  [R_0402]  298.56 127.44 90 top
R1668  -  [R_0402]  339.96 164.53 90 top
R1669  -  [R0402_0OHM]  300.34 127.44 90 top
R1670  -  [R_0402]  299.45 127.44 90 top
R1672  -  [R0402_0OHM]  186.93 185.51 270 top
R1673  -  [R0402_0OHM]  187.94 185.51 270 top
R1676  -  [R_0402]  350.85 177.09 90 bottom
R1677  -  [R_0402]  348.61 179.06 270 bottom
R1679  -  [R_0402]  352.41 174.33 270 top
R1680  -  [R_0402]  343.01 172.68 270 bottom
R1681  -  [R_0402]  341.99 172.68 270 bottom
R1682  -  [R_0402]  340.09 172.68 270 bottom
R1683  -  [R_0402]  340.98 172.68 270 bottom
R1684  -  [R_0402]  322.64 137.43 90 top
R1685  -  [R_0402]  326.4 128.98 0 top
R1686  -  [R_0402]  326.4 127.09 0 top
R1687  -  [R_0402]  318.24 133.81 0 top
R1688  -  [R_0402]  319.18 129.1 180 top
R1689  -  [R_0402]  319.16 131.81 180 top
R1700  -  [R_0402]  244.76 45.1 0 top
R1701  -  [R_0402]  245.68 46.11 180 top
R1702  -  [R_0402]  248.6 40.04 270 top
R3664  -  [R_0402]  194.42 26.23 90 top
R3665  -  [R_0402]  201.79 26.23 90 top
R3666  -  [R_0402]  201.65 39.48 90 top
R3667  -  [R_0402]  199.75 26.23 90 top
R3668  -  [R_0402]  191.37 40.98 270 top
R3669  -  [R_0402]  192.39 40.07 90 top
R3671  -  [R_0402]  324.21 166.81 90 top
R3672  -  [R_0402]  52.94 196.28 90 top
R3673  -  [R_0402]  327.01 184.85 90 bottom
R3674  -  [R_0402]  323.76 186.07 0 bottom
R3675  -  [R_0402]  323.76 190.13 0 bottom
R3676  -  [R_0402]  323.76 187.08 0 bottom
R3677  -  [R_0402]  323.76 193.18 0 bottom
R3678  -  [R_0402]  325.99 194.91 270 bottom
R3679  -  [R_0402]  334.58 193.18 180 bottom
R3680  -  [R_0402]  328.02 194.91 270 bottom
R3681  -  [R_0402]  329.04 194.91 270 bottom
R3682  -  [R_0402]  324.67 185.05 180 bottom
R3683  -  [R_0402]  324.67 189.12 180 bottom
R3684  -  [R_0402]  324.67 188.1 180 bottom
R3685  -  [R_0402]  324.67 192.16 180 bottom
R3686  -  [R_0402]  327.01 193.99 90 bottom
R3687  -  [R_0402]  333.66 194.2 0 bottom
R3688  -  [R_0402]  324.67 191.15 180 bottom
R3689  -  [R_0402]  347.28 215.79 0 bottom
R3690  -  [R_0402]  347.28 214.77 0 bottom
R3691  -  [R_0402]  348.14 218.71 0 bottom
R3692  -  [R_0402]  334.58 188.1 180 bottom
R3693  -  [R_0402]  334.58 192.16 180 bottom
R3694  -  [R_0402]  334.58 189.12 180 bottom
R3695  -  [R_0402]  334.58 185.05 180 bottom
R3696  -  [R_0402]  348.14 219.72 0 bottom
R3697  -  [R_0402]  348.14 216.8 0 bottom
R3698  -  [R_0402]  348.14 217.82 0 bottom
R3699  -  [R_0402]  333.66 187.08 0 bottom
R3700  -  [R_0402]  333.66 191.15 0 bottom
R3701  -  [R_0402]  333.66 190.13 0 bottom
R3702  -  [R_0402]  333.66 186.07 0 bottom
R3703  -  [R_0402]  343.72 218.07 180 bottom
R3704  -  [R_0402]  341.61 214.69 90 bottom
R3705  -  [R_0402]  337.55 214.69 90 bottom
R3706  -  [R_0402]  338.56 214.69 90 bottom
R3707  -  [R_0402]  334.5 214.69 90 bottom
R3708  -  [R_0402]  333.28 217.06 0 bottom
R3709  -  [R_0402]  332.39 223.02 0 bottom
R3710  -  [R_0402]  350.12 187.13 90 bottom
R3711  -  [R_0402]  349.11 187.13 90 bottom
R3712  -  [R_0402]  333.28 218.07 0 bottom
R3713  -  [R_0402]  333.28 219.09 0 bottom
R3714  -  [R_0402]  340.6 215.61 270 bottom
R3715  -  [R_0402]  336.53 215.61 270 bottom
R3716  -  [R_0402]  339.58 215.61 270 bottom
R3717  -  [R_0402]  333.48 215.61 270 bottom
R3718  -  [R_0402]  332.47 215.61 270 bottom
R3719  -  [R_0402]  334.25 223.08 90 bottom
R3720  -  [R_0402]  335.52 215.61 270 bottom
R3721  -  [R_0402]  348.9 195.97 0 bottom
R3722  -  [R_0402]  348.9 196.99 0 bottom
R3723  -  [R_0402]  340.34 223.99 270 bottom
R3724  -  [R_0402]  336.28 223.99 270 bottom
R3725  -  [R_0402]  337.29 223.99 270 bottom
R3726  -  [R_0402]  341.36 223.99 270 bottom
R3727  -  [R_0402]  348.9 193.94 0 bottom
R3728  -  [R_0402]  348.9 194.96 0 bottom
R3729  -  [R_0402]  339.33 223.08 90 bottom
R3730  -  [R_0402]  335.26 223.08 90 bottom
R3731  -  [R_0402]  338.31 223.08 90 bottom
R3732  -  [R_0402]  342.37 223.08 90 bottom
R3733  -  [R_0402]  34.91 189.83 270 bottom
R3734  -  [R_0402]  37.19 179.67 270 bottom
R3735  -  [R_0402]  38.21 178.75 90 bottom
R3736  -  [R_0402]  39.99 188.91 90 bottom
R3737  -  [R_0402]  35.16 178.75 90 bottom
R3738  -  [R_0402]  31.1 178.75 90 bottom
R3739  -  [R_0402]  37.96 189.83 270 bottom
R3740  -  [R_0402]  36.94 188.91 90 bottom
R3741  -  [R_0402]  30.08 179.67 270 bottom
R3742  -  [R_0402]  31.01 180.98 180 bottom
R3743  -  [R_0402]  41 188.91 90 bottom
R3744  -  [R_0402]  30.13 182 0 bottom
R3745  -  [R_0402]  35.92 188.91 90 bottom
R3746  -  [R_0402]  33.89 189.83 270 bottom
R3747  -  [R_0402]  42.02 189.83 270 bottom
R3748  -  [R_0402]  36.18 179.67 270 bottom
R3749  -  [R_0402]  32.88 188.91 90 bottom
R3750  -  [R_0402]  34.15 178.75 90 bottom
R3751  -  [R_0402]  33.13 179.67 270 bottom
R3752  -  [R_0402]  38.97 189.83 270 bottom
R3753  -  [R0402_0OHM]  30.13 183.02 0 bottom
R3754  -  [R_0402]  40.95 182 180 bottom
R3755  -  [R_0402]  32.11 179.67 270 bottom
R3756  -  [R0402_0OHM]  30.13 184.04 0 bottom
R3757  -  [R_0402]  339.34 197.24 90 bottom
R3758  -  [R_0402]  336.22 189.32 0 bottom
R3759  -  [R_0402]  345.91 190.64 0 bottom
R3760  -  [R_0402]  337.13 194.91 180 bottom
R3761  -  [R_0402]  345.91 192.67 0 bottom
R3762  -  [R_0402]  346.82 191.66 180 bottom
R3763  -  [R_0402]  341.37 195.87 270 bottom
R3764  -  [R_0402]  337.13 190.21 180 bottom
R3765  -  [R_0402]  337.13 188.43 180 bottom
R3766  -  [R_0402]  337.13 192.87 180 bottom
R3767  -  [R_0402]  336.22 191.1 0 bottom
R3768  -  [R_0402]  346.82 184.54 180 bottom
R3769  -  [R_0402]  339.35 186.21 90 bottom
R3770  -  [R_0402]  340.36 195.87 270 bottom
R3771  -  [R_0402]  346.82 193.69 180 bottom
R3772  -  [R_0402]  336.22 191.99 0 bottom
R3773  -  [R_0402]  345.91 186.58 0 bottom
R3774  -  [R_0402]  346.82 187.59 180 bottom
R3775  -  [R_0402]  337.13 193.89 180 bottom
R3776  -  [R_0402]  345.91 185.56 0 bottom
R3777  -  [R_0402]  336.22 195.92 0 bottom
R3778  -  [R_0402]  339.34 195.87 270 bottom
R3779  -  [R_0402]  345.91 189.62 0 bottom
R3780  -  [R_0402]  346.82 188.61 180 bottom
R3881  -  [R0805_0OHM]  180.78 132.51 270 bottom
R3882  -  [R0805_0OHM]  172.18 142.63 180 bottom
R3883  -  [R0805_0OHM]  174.82 130.1 90 top
RC1  -  [R_0402]  166.08 99.94 270 top
RC2  -  [R0402_0OHM]  175.42 109.11 0 top
RC3  -  [R0402_0OHM]  176.18 110.12 0 top
RC4  -  [R_0402]  136.89 66.26 0 top
RC5  -  [R_0402]  137.52 64.86 270 top
RC6  -  [R_0402]  144.38 63.94 90 top
RC7  -  [R_0402]  137.52 62.32 270 top
RC8  -  [R_0402]  122.33 119.01 0 bottom
RC9  -  [R_0402]  144.38 66.48 90 top
RC10  -  [R0402_0OHM]  142.35 63.94 90 top
RC11  -  [R_0402]  114.23 114.57 180 top
RC12  -  [R_0402]  136.89 67.14 0 top
RC13  -  [R_0402]  139.31 60.01 270 top
RC14  -  [R0402_0OHM]  138.21 60.01 270 top
RC15  -  [R_0402]  143.37 67.4 270 top
RC16  -  [R_0402]  143.37 64.86 270 top
RC20  -  [R_0402]  114.23 110.5 180 top
RC21  -  [R_0402]  114.23 111.52 180 top
RC22  -  [R_0402]  114.23 113.55 180 top
RC23  -  [R_0402]  123.25 116.47 180 bottom
RC24  -  [R_0402]  114.23 115.58 180 top
RC25  -  [R_0402]  114.23 116.6 180 top
RC26  -  [R_0402]  114.23 117.61 180 top
RC27  -  [R_0402]  134.48 122.77 270 bottom
RC28  -  [R_0402]  133.46 120.99 270 top
RC29  -  [R_0402]  129.4 123.79 270 top
RC30  -  [R_0402]  129.4 120.99 270 top
RC31  -  [R0402_0OHM]  134.48 119.98 270 bottom
RC32  -  [R_0402]  131.89 103.01 180 top
RC33  -  [R0402_0OHM]  136.51 123.79 270 top
RC34  -  [R_0402]  135.49 120.08 90 top
RC35  -  [R0402_0OHM]  131.43 120.99 270 top
RC36  -  [R_0402]  131.89 106.06 180 bottom
RC37  -  [R_0402]  130.41 120.08 90 top
RC42  -  [R0402_0OHM]  178.21 104.79 0 top
RC44  -  [R0402_0OHM]  178.21 106.06 0 top
RC46  -  [R0402_0OHM]  175.42 103.77 0 top
RC48  -  [R0402_0OHM]  175.42 102.76 0 top
RC52  -  [R_0402]  131.43 123.79 270 top
RC53  -  [R_0402]  132.44 120.99 270 top
RC54  -  [R_0402]  128.43 103.01 0 top
RC55  -  [R_0402]  130.97 104.03 0 top
RC56  -  [R_0402]  137.52 122.87 90 top
RC57  -  [R_0402]  123.25 118 180 bottom
RC58  -  [R_0402]  131.95 85.99 180 top
RC59  -  [R_0402]  134.48 123.79 270 top
RC60  -  [R_0402]  129.09 100.98 180 bottom
RC61  -  [R_0402]  131.95 84.98 180 top
RC62  -  [R_0402]  134.48 120.99 270 top
RC63  -  [R_0402]  131.95 83.96 180 top
RC64  -  [R_0402]  128.18 103.01 0 bottom
RC66  -  [R0402_0OHM]  131.89 104.03 180 bottom
RC67  -  [R_0402]  128.18 101.99 0 bottom
RC68  -  [R_0402]  174.79 92.8 0 top
RC69  -  [R_0402]  175.7 93.69 180 top
RC73  -  [R_0402]  166.08 100.8 90 top
RC74  -  [R_0402]  163.69 124.04 270 top
RC75  -  [R_0402]  163.2 129.96 0 top
RC76  -  [R_0402]  131.89 97.93 180 top
RC77  -  [R_0402]  131.89 100.98 180 bottom
RC78  -  [R_0402]  131.89 98.95 180 top
RC79  -  [R_0402]  131.89 101.99 180 bottom
RC80  -  [R_0402]  162.67 123.13 90 top
RC81  -  [R_0402]  131.89 107.07 180 bottom
RC82  -  [R_0402]  165.24 104.23 0 top
RC83  -  [R_0402]  129.35 100.98 180 top
RC84  -  [R_0402]  153.75 72.21 270 top
RC85  -  [R_0402]  176.34 101.74 180 top
RC86  -  [R_0603]  129.33 95.9 180 top
RC87  -  [R_0402]  130.97 95.9 0 top
RC88  -  [R_0402]  130.97 96.91 0 top
RC89  -  [R_0402]  175.42 100.72 0 top
RC90  -  [R_0402]  130.97 99.96 0 top
RC91  -  [R_0402]  135.49 122.77 270 bottom
RC92  -  [R0402_0OHM]  135.49 119.06 90 bottom
RC93  -  [R0402_0OHM]  136.51 119.06 90 bottom
RC94  -  [R_0402]  136.51 121.86 90 bottom
RC95  -  [R_0402]  143.37 71.56 90 top
RC96  -  [R_0402]  143.37 69.02 90 top
RC97  -  [R_0402]  139.3 72.48 270 top
RC98  -  [R_0402]  144.38 69.02 90 top
RC99  -  [R_0603]  128.13 119.07 90 bottom
RC100  -  [R_0402]  129.35 97.93 180 top
RC103  -  [R_0402]  141.59 58 270 top
RC104  -  [R_0402]  139.3 58 270 top
RC105  -  [R0603_0OHM]  180.79 101.08 270 bottom
RC106  -  [R_0603]  177.82 98.25 90 bottom
RC108  -  [R_0402]  127.08 25.79 270 top
RC109  -  [R_0402]  125.84 32.09 270 top
RC110  -  [R_0402]  169.17 17.68 270 top
RC143  -  [R_0402]  144.38 72.48 270 top
RD1  -  [R0402_0OHM]  121.1 37.35 90 top
RD2  -  [R_0402]  134.41 17.45 180 top
RD3  -  [R_0402]  120.21 37.35 90 top
RD4  -  [R0402_0OHM]  132.62 17.44 90 top
RD5  -  [R_0402]  163.89 22.02 180 top
RD6  -  [R0402_0OHM]  184.07 36.54 0 top
RD7  -  [R0402_0OHM]  184.07 37.93 0 top
RD8  -  [R0402_0OHM]  125.51 25.93 270 top
RD9  -  [R_0402]  124.58 23.25 90 top
RD10  -  [R_0402]  163.11 18.38 0 top
RD11  -  [R0402_0OHM]  184.71 22.64 270 top
RD12  -  [R0402_0OHM]  185.67 23.76 90 top
RD13  -  [R0402_0OHM]  165.72 22.67 90 top
RD14  -  [R_0402]  128.08 26.81 180 top
RD15  -  [R_0402]  128.08 28.59 180 top
RD16  -  [R_0402]  127.16 27.7 0 top
RD17  -  [R_0402]  123.81 31.18 90 top
RD18  -  [R_0402]  122.79 32.09 270 top
RD19  -  [R_0402]  126.86 31.18 90 top
RD20  -  [R_0402]  167.24 15.58 270 top
RD21  -  [R_0402]  166.23 14.67 90 top
RD22  -  [R_0402]  165.21 15.58 270 top
RD23  -  [R0402_0OHM]  164.19 14.67 90 top
RD24  -  [R_0402]  133.5 18.33 0 top
RD25  -  [R0402_0OHM]  129.95 19.66 0 top
RD26  -  [R0402_0OHM]  124.02 30.29 180 top
RD27  -  [R_0402]  121.59 29.29 270 top
RD28  -  [R_0402]  166.49 20.59 180 top
RD29  -  [R0402_0OHM]  166.51 19.34 180 top
RD30  -  [R_0402]  124.35 26.92 0 top
RD31  -  [R0402_0OHM]  122.54 26.92 0 top
RE1  -  [R_0402]  194.42 40.07 90 top
RE2  -  [R_0402]  202.98 40.39 270 top
RE3  -  [R0402_0OHM]  250.3 35.39 270 top
RE4  -  [R0402_0OHM]  251.32 35.39 270 top
RE5  -  [R_0402]  295 128.36 270 top
RE7  -  [R_0402]  168.77 177.38 270 bottom
RE8  -  [R_0402]  169.78 177.38 270 bottom
RE9  -  [R_0402]  170.8 177.38 270 bottom
RE10  -  [R_0402]  171.81 177.38 270 bottom
RE11  -  [R_0402]  190.36 177.63 270 bottom
RE12  -  [R_0402]  187.31 177.63 270 bottom
RE13  -  [R_0402]  172.83 177.38 270 bottom
RE14  -  [R_0402]  173.85 177.38 270 bottom
RE15  -  [R_0402]  174.86 177.38 270 bottom
RE16  -  [R_0402]  175.88 177.38 270 bottom
RE17  -  [R_0402]  168.26 190.59 270 top
RE18  -  [R_0402]  169.27 190.59 270 top
RE19  -  [R_0402]  170.29 190.59 270 top
RE20  -  [R_0402]  171.31 190.59 270 top
RE21  -  [R_0402]  172.32 190.59 270 top
RE22  -  [R_0402]  173.34 190.59 270 top
RE23  -  [R_0402]  174.35 190.59 270 top
RE24  -  [R_0402]  175.37 190.59 270 top
RE25  -  [R0402_0OHM]  252.33 35.39 270 top
RE26  -  [R0402_0OHM]  253.35 35.39 270 top
RE27  -  [R0402_0OHM]  248.27 35.39 270 top
RE28  -  [R0402_0OHM]  249.28 35.39 270 top
RE29  -  [R0402_0OHM]  256.07 46.88 0 top
RE30  -  [R0402_0OHM]  256.04 48.22 0 top
RE32  -  [R0603_0OHM]  178.7 154.85 0 bottom
RH1  -  [R_0402]  122.33 113.42 0 bottom
RH2  -  [R_0402]  122.33 114.44 0 bottom
RH3  -  [R_0402]  276 90.56 0 top
RH4  -  [R_0402]  276 89.55 0 top
RH5  -  [R_0402]  210.62 52.1 45 top
RH6  -  [R_0402]  276 88.53 0 top
RH7  -  [R_0402]  276 87.52 0 top
RH8  -  [R_0402]  276 86.5 0 top
RH9  -  [R_0402]  276 85.48 0 top
RH10  -  [R_0402]  276 83.45 0 top
RH11  -  [R_0402]  271.51 90 270 top
RH12  -  [R_0402]  188.99 66.84 225 bottom
RH13  -  [R_0402]  269.48 88.33 90 top
RH14  -  [R_0402]  191.7 59.14 225 bottom
RH16  -  [R_0402]  270.16 84.98 0 top
RH17  -  [R_0402]  276 84.47 0 top
RH18  -  [R_0402]  211.89 52.12 225 top
RH19  -  [R_0402]  196 64.47 315 top
RH20  -  [R_0402]  194.11 65.11 225 top
RH22  -  [R_0402]  195.35 62.61 45 top
RH24  -  [R_0402]  200.04 53.46 225 top
RH25  -  [R_0402]  190.47 64.91 225 top
RH26  -  [R_0402]  276 82.44 0 top
RH27  -  [R_0402]  270.16 80.66 0 top
RH28  -  [R_0402]  276 81.42 0 top
RH30  -  [R_0402]  276 79.26 0 top
RH31  -  [R_0402]  276 78.24 0 top
RH32  -  [R_0402]  271.08 77.61 180 top
RH34  -  [R_0402]  188.18 69.88 135 top
RH35  -  [R_0402]  219.75 61.22 135 bottom
RH36  -  [R_0402]  190.07 69.18 225 bottom
RH37  -  [R_0402]  188.36 67.46 135 bottom
RH38  -  [R0402_0OHM]  208.88 55.7 135 top
RH39  -  [R_0402]  207.28 57.2 135 top
RH40  -  [R_0402]  215 63.84 315 top
RH41  -  [R_0402]  216.61 64.36 135 top
RH42  -  [R_0402]  209.94 55.83 45 top
RH43  -  [R_0402]  211.56 56.54 45 bottom
RH44  -  [R_0402]  209.31 56.45 45 top
RH45  -  [R_0402]  221.16 58.24 135 bottom
RH46  -  [R_0603]  195 58.17 135 bottom
RH47  -  [R_0402]  196.85 59.08 225 bottom
RH48  -  [R_0402]  194.86 59.78 45 bottom
RH50  -  [R_0402]  194.18 60.45 45 bottom
RH51  -  [R0402_0OHM]  192.84 73.58 315 top
RH52  -  [R_0402]  271.08 78.63 180 top
RH53  -  [R0402_0OHM]  205.31 57.87 45 top
RH54  -  [R_0402]  197.34 61.91 225 bottom
RH55  -  [R_0402]  196.67 62.58 225 bottom
RH56  -  [R_0402]  270.16 79.64 0 top
RH57  -  [R_0402]  192.85 72.3 135 top
RH58  -  [R_0402]  219.64 56.71 135 bottom
RH59  -  [R_0402]  220.4 57.47 135 bottom
RH60  -  [R_0402]  203.12 50.08 45 bottom
RH61  -  [R_0402]  202.49 50.71 45 bottom
RH62  -  [R_0402]  219.1 60.57 135 bottom
RH63  -  [R_0402]  218.47 59.94 135 bottom
RH64  -  [R_0402]  221.05 63.7 225 bottom
RH65  -  [R_0402]  220.38 61.84 135 bottom
RH66  -  [R0402_0OHM]  192.81 63.01 135 bottom
RH67  -  [R_0402]  211.58 57.82 225 bottom
RH70  -  [R_0402]  187.73 65.57 135 bottom
RH73  -  [R_0402]  195.99 58.43 45 top
RH75  -  [R_0402]  198.76 57.15 315 top
RH76  -  [R_0402]  190.83 60.96 225 top
RH78  -  [R_0402]  200.69 57.26 45 top
RH79  -  [R_0402]  205.68 55.69 45 bottom
RH80  -  [R_0402]  199.59 51.13 225 bottom
RH81  -  [R_0402]  212.21 58.47 315 bottom
RH85  -  [R_0402]  212.27 53.28 135 bottom
RH87  -  [R_0402]  209.74 52.75 225 bottom
RH88  -  [R_0402]  223.52 76.59 225 bottom
RH89  -  [R_0402]  222.89 77.22 225 bottom
RH90  -  [R_0402]  191.07 62.69 315 top
RH91  -  [R_0402]  203.35 55.88 225 top
RH92  -  [R_0402]  201.36 56.59 45 top
RH93  -  [R_0402]  204.84 45.68 135 top
RH94  -  [R_0402]  219.66 75.49 135 top
RH95  -  [R_0402]  218.67 74.51 135 top
RH96  -  [R0402_0OHM]  208.75 91.36 225 bottom
RH97  -  [R_0402]  216.19 76.52 45 top
RH98  -  [R0402_0OHM]  197.25 77.89 225 top
RH99  -  [R_0402]  209.38 90.73 225 bottom
RH100  -  [R_0402]  197.24 76.63 315 top
RH101  -  [R0402_0OHM]  203.86 53.79 135 top
RH102  -  [R0402_0OHM]  196.77 57.88 45 top
RH103  -  [R0402_0OHM]  212.3 53.31 135 top
RH104  -  [R0402_0OHM]  206.31 55.06 45 bottom
RH105  -  [R0402_0OHM]  205.05 56.32 45 bottom
RH106  -  [R0402_0OHM]  196.12 56.09 45 top
RH107  -  [R0402_0OHM]  202.03 55.9 45 top
RH108  -  [R0402_0OHM]  204.93 59.43 135 top
RH109  -  [R0402_0OHM]  185.07 68.6 315 top
RH110  -  [R0402_0OHM]  183.81 67.26 315 top
RH111  -  [R0402_0OHM]  184.44 67.97 315 top
RH112  -  [R_0402]  200.42 51.96 45 top
RH113  -  [R0402_0OHM]  185.7 69.22 315 top
RH114  -  [R0402_0OHM]  186.33 69.85 315 top
RH115  -  [R_0402]  222.18 77.93 225 bottom
RH116  -  [R_0402]  221.41 78.69 225 bottom
RH117  -  [R_0402]  220.65 79.46 225 bottom
RH118  -  [R_0402]  224.28 65.66 135 top
RH119  -  [R_0402]  213.48 58.45 135 bottom
RH120  -  [R_0402]  202.72 56.55 225 bottom
RH122  -  [R_0402]  198.68 60.66 225 bottom
RH125  -  [R_0402]  194.54 64.31 45 top
RH128  -  [R_0402]  195.96 59.75 225 top
RH133  -  [R_0402]  195.35 62.61 45 bottom
RH136  -  [R_0402]  222.34 65 315 top
RH138  -  [R_0402]  222.96 65.63 315 top
RH141  -  [R_0402]  192.99 75.31 135 bottom
RH143  -  [R_0402]  192 74.33 135 bottom
RH146  -  [R_0402]  223.41 74.68 45 bottom
RH152  -  [R0402_0OHM]  214.51 87.75 135 bottom
RH153  -  [R_0402]  214.51 86.47 45 bottom
RH155  -  [R_0402]  224.46 69.67 135 bottom
RH157  -  [R_0402]  220.87 69.34 135 top
RH158  -  [R_0402]  220.45 73.42 45 top
RH159  -  [R_0402]  220.24 68.71 135 top
RH160  -  [R_0402]  219.82 74.05 45 top
RH161  -  [R_0402]  221.5 69.97 135 top
RH162  -  [R_0402]  221.06 72.78 45 top
RH163  -  [R0402_0OHM]  211.87 82.63 45 top
RH164  -  [R_0402]  223.05 69.55 315 bottom
RH165  -  [R_0402]  212.28 86.45 45 bottom
RH166  -  [R_0402]  196.04 54.68 225 bottom
RH167  -  [R_0402]  190.16 60.27 135 bottom
RH168  -  [R_0402]  191.53 66.42 45 top
RH169  -  [R_0402]  186.46 65.59 315 bottom
RH170  -  [R_0402]  197.07 53.64 225 bottom
RH171  -  [R_0402]  198.96 51.76 225 bottom
RH172  -  [R_0402]  197.68 51.74 45 bottom
RH173  -  [R_0402]  197.06 52.37 45 bottom
RH174  -  [R_0402]  194.41 57.73 225 top
RH175  -  [R_0402]  195.04 57.1 225 top
RH176  -  [R_0402]  205.22 90.16 135 bottom
RH177  -  [R0402_0OHM]  209.63 42.35 90 bottom
RH178  -  [R0402_0OHM]  208.61 42.35 90 bottom
RH179  -  [R0402_0OHM]  207.6 42.35 90 bottom
RH180  -  [R_0402]  195.44 27.14 270 top
RH181  -  [R0402_0OHM]  206.58 42.35 90 bottom
RH182  -  [R0402_0OHM]  205.56 42.35 90 bottom
RH183  -  [R0402_0OHM]  204.55 42.35 90 bottom
RH184  -  [R0402_0OHM]  203.53 42.35 90 bottom
RH185  -  [R0402_0OHM]  201.75 42.35 90 bottom
RH186  -  [R_0402]  200.77 27.14 270 top
RH187  -  [R_0402]  211.96 68.19 315 top
RH188  -  [R0402_0OHM]  200.32 84.03 315 bottom
RH189  -  [R0402_0OHM]  204.03 53.87 225 bottom
RH190  -  [R0402_0OHM]  198.73 59.25 45 bottom
RH191  -  [R0402_0OHM]  202.71 55.24 45 bottom
RH192  -  [R_0402]  202.98 80.37 45 top
RH193  -  [R_0402]  190.9 67.05 45 top
RH194  -  [R_0402]  190.05 67.9 45 top
RH195  -  [R0402_0OHM]  189.2 64.9 45 top
RH196  -  [R0402_0OHM]  219.71 55.31 315 bottom
RH197  -  [R_0402]  192.97 58.12 225 bottom
RH198  -  [R_0402]  189.4 69.85 225 top
RH199  -  [R_0402]  189.42 68.53 45 top
RH200  -  [R_0402]  194.68 63.28 45 bottom
RH201  -  [R_0402]  217.1 58.21 135 top
RH202  -  [R_0402]  212.28 54.59 315 top
RH203  -  [R_0402]  212.91 55.22 315 top
RH204  -  [R_0402]  188.68 64.2 225 top
RH205  -  [R_0402]  190.02 62.85 225 top
RH206  -  [R_0402]  192.57 70.08 315 top
RH207  -  [R_0402]  210.44 62.53 315 top
RH208  -  [R_0402]  211.07 63.16 315 top
RH211  -  [R_0402]  198.76 53.45 45 top
RH212  -  [R_0402]  194.77 54.66 45 bottom
RH213  -  [R_0402]  197.68 51.74 45 top
RH215  -  [R_0402]  217.01 56.88 225 top
RH216  -  [R_0402]  218.87 55.95 135 bottom
RH217  -  [R_0402]  218.11 55.19 135 bottom
RH222  -  [R_0402]  197.52 55.98 225 top
RH223  -  [R_0402]  195.4 55.31 315 top
RH224  -  [R_0402]  192.16 65.79 45 bottom
RH225  -  [R_0402]  195.37 63.88 225 top
